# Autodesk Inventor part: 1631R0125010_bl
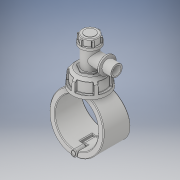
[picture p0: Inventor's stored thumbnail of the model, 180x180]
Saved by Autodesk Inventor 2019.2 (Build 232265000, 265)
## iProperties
Created: 2022-02
Part Number: 1631R0125010_bl
Material: Generic
Description: Plassadle Tapper Male 125x1''
Document SubType Name: Modeling
Designer: comp2
Density: 1 g/cm^3
Appearance: Default
Author: comp2
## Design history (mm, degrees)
derived "1631R.ipt"
feature "Solid1::1631R.ipt" dims "ScaleForDerivedMember" = 10
feature "Solid2::1631R.ipt" dims "ScaleForDerivedMember" = 10
feature "Solid3::1631R.ipt" dims "ScaleForDerivedMember" = 10
feature "Solid4::1631R.ipt" dims "ScaleForDerivedMember" = 10
tag "TaggingFeature1"
body "Solid1"
body "Solid2"
body "Solid3"
body "Solid4"
other parameters: "d0" = 125 [user parameter], "d2" = 157 [user parameter], "d3" = 62.5 [user parameter], "d7" = 149.15 [user parameter], "d8" = 85 deg [user parameter], "d9" = 45 deg [user parameter], "d10" = 102 [user parameter], "d11" = 49 [user parameter], "d12" = 34.3 [user parameter], "d13" = 42.84 [user parameter], "d14" = 57.936 [user parameter], "d15" = 2.45 [user parameter], "d16" = 2 [user parameter], "d17" = 2 [user parameter], "d18" = 29.4 [user parameter], "d19" = 7.35 [user parameter], "d20" = 1 [user parameter], "d21" = 30.6 [user parameter], "d22" = 1 [user parameter], "d23" = 14.7 [user parameter], "d24" = 78 [user parameter], "d27" = 144 [user parameter], "d29" = 49.8735 [user parameter], "d31" = 33.249 [user parameter], "d32" = 31.2 [user parameter], "d33" = 26.52 [user parameter], "d41" = 5 [user parameter], "d42" = 3.2 [user parameter], "d46" = 56.1 [user parameter], "d47" = 36.5739 [user parameter], "d48" = 49 [user parameter], "d49" = 3.14 [user parameter], "d51" = 0 [user parameter], "d52" = 22.4 [user parameter], "d53" = 86.35 [user parameter], "d54" = 35 [user parameter], "d55" = 0 [user parameter], "d59" = 0 [user parameter], "d61" = 0 [user parameter], "d62" = 35 [user parameter], "d63" = 0 [user parameter], "d65" = 0 [user parameter], "d67" = 0 [user parameter], "d69" = 0 [user parameter], "d70" = 1 [user parameter], "d71" = 96 [user parameter], "d72" = 0 [user parameter], "d73" = 2 [user parameter], "d77" = 24.93675 [user parameter], "d78" = 86.7 [user parameter], "d79" = 5.1 [user parameter], "d80" = 60 deg [user parameter], "d81" = 5.1 [user parameter], "d84" = 0 [user parameter], "d85" = 1 [user parameter], "d87" = 360 deg [user parameter], "d90" = 0 [user parameter], "d91" = 1 [user parameter], "d93" = 60 deg [user parameter], "d94" = 3.06 [user parameter], "d95" = 3.06 [user parameter], "d97" = 0 [user parameter], "d98" = 0.5 [user parameter], "d100" = 360 deg [user parameter], "d102" = 2 [user parameter], "d117" = 0.5 [user parameter], "d118" = 31.2 [user parameter], "d119" = 100 deg [user parameter], "d121" = 0 [user parameter], "d" = 125 [user parameter], "d1" = 25 [user parameter], "B" = 157 [user parameter], "E_" = 54 [user parameter], "E1" = 102 [user parameter], "H2" = 144 [user parameter], "H3" = 78 [user parameter], "H_costum" = 49 [user parameter], "R" = 33.249 [user parameter]
